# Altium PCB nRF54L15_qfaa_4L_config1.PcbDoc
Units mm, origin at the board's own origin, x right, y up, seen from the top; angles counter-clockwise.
Board outline 15 x 13 mm, 4 copper layers (Top Layer, Mid-Layer 1, Mid-Layer 2, Bottom Layer), stack 1.54 mm thick; 22 components, 46 nets, 93 pads, 72 vias.
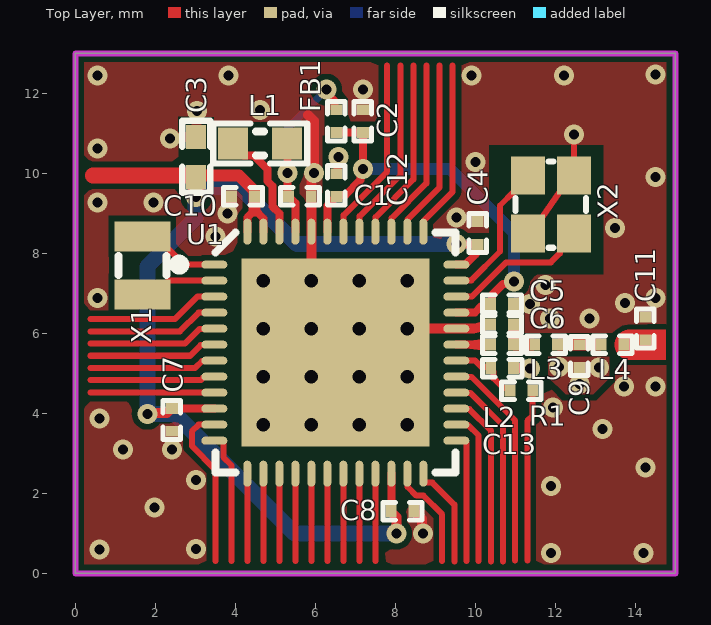
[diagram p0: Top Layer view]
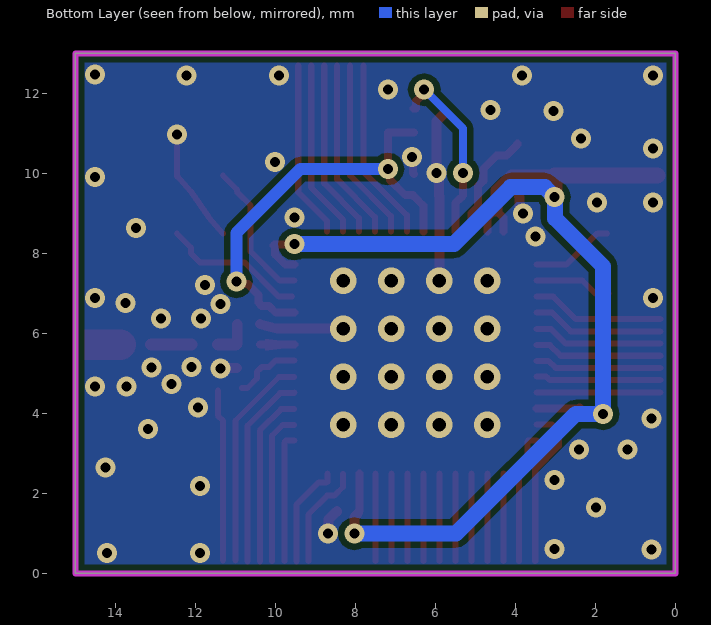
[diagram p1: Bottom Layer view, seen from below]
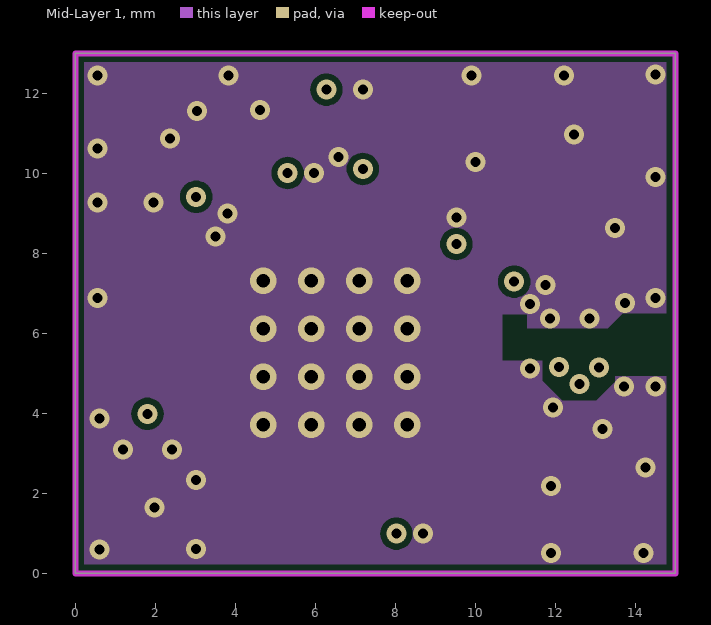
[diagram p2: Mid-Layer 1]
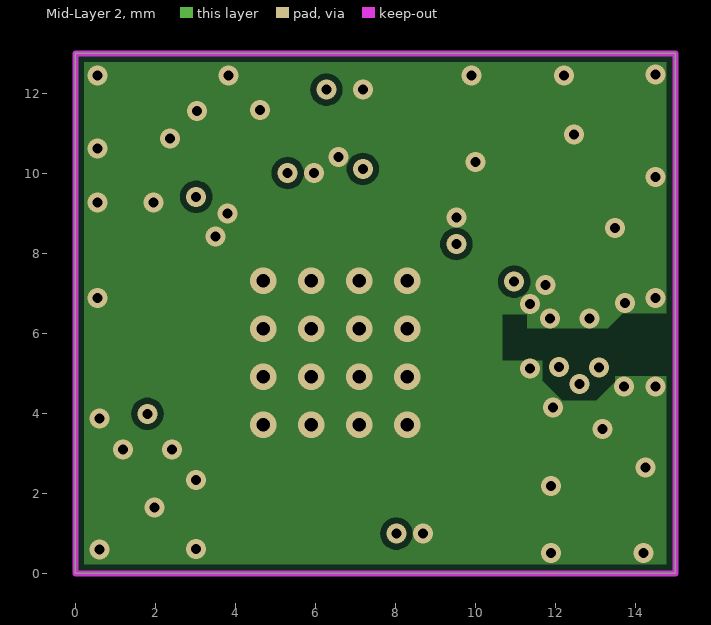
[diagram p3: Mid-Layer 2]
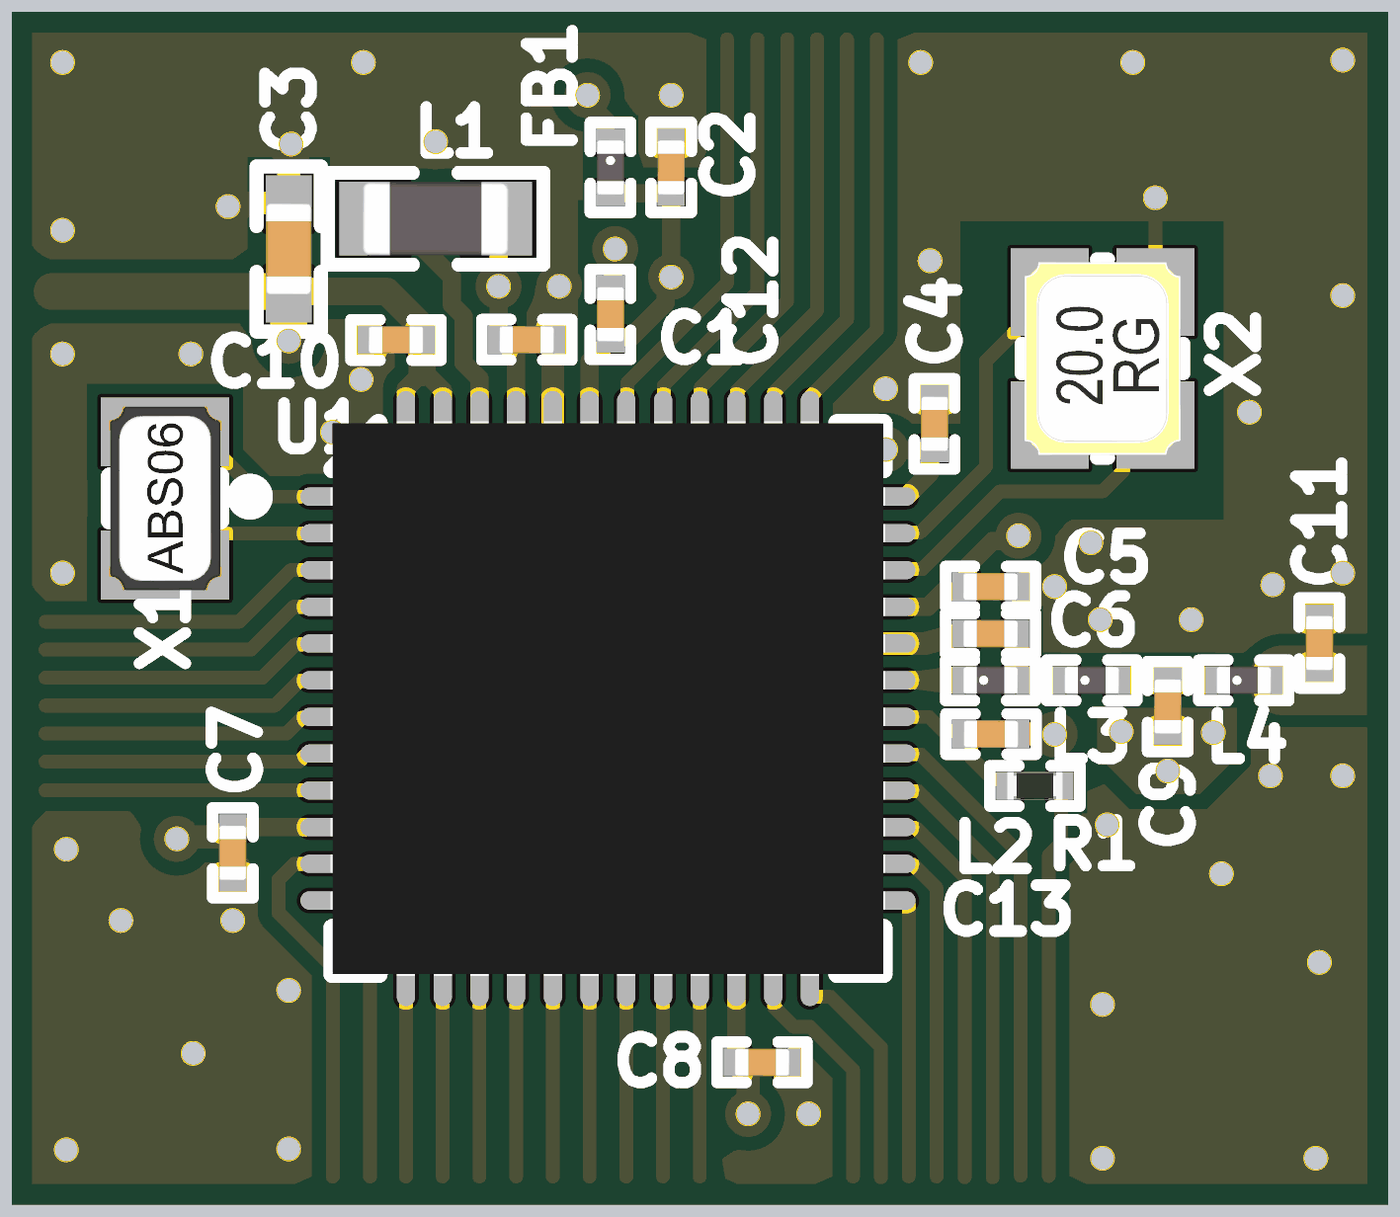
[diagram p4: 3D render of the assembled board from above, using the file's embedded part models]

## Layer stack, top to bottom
Top Solder: solder mask 0.0102, Solder Resist, Dk 3.5
Top Layer: signal copper 0.035
Dielectric 1: prepreg 0.1, PP-018, Dk 4.3
Mid-Layer 1: signal copper 0.035
Dielectric 2: core 1.2, Core-042, Dk 4.6
Mid-Layer 2: signal copper 0.035
Dielectric 3: prepreg 0.1, PP-018, Dk 4.3
Bottom Layer: signal copper 0.035
Bottom Solder: solder mask 0.0102, Solder Resist, Dk 3.5

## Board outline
0,0 0,13 15,13 15,0

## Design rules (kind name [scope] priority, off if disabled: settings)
Clearance Polygon_ANT [(InNamedPolygon('Top_Layer-GND')) or IsFill or IsRegion vs InNet('RF')] p1: gap=0.127 ignorepadtopadclearanceinfootprint=FALSE
Clearance Polygon [(InNamedPolygon('Top_Layer-GND'))  or (InNamedPolygon('Bottom_Layer-GND'))] p2: gap=0.15 ignorepadtopadclearanceinfootprint=FALSE
Clearance [All] p3: gap=0.15 ignorepadtopadclearanceinfootprint=FALSE
ComponentClearance [All] p1 off: gap=0.254 collisioncheckmode=3 verticalgap=0.254 showdistances=FALSE
FabricationTestPointUsage TestPointUsage [All] p1: valid=0 allowmultiple=FALSE
FabricationTestpoint Testpoint [All] p1: side=3 testpointundercomponent=TRUE minsize=1.016 maxsize=2.54 preferedsize=1.524 minholesize=0 maxholesize=1.016 preferedholesize=0.813 testpointgrid=0.025 allowsidetop=TRUE allowsidebottom=TRUE usegrid=TRUE gridtolerance=0
Height [All] p1 off: minheight=0 maxheight=25.4 prefheight=12.7
HoleSize [All] p1: absolutevalues=TRUE maxlimit=4.064 minlimit=0.2 maxpercent=80.000 minpercent=20.000
HoleToHoleClearance [All] p1: gap=0.36 allowstackedmicrovias=TRUE
MinimumAnnularRing [All] p1 off: minimumring=0.152
MinimumSolderMaskSliver [All] p1: minsoldermaskwidth=0.11
PlaneClearance [All] p1: clearance=0.2
PolygonConnect PolygonConnect_SMD_PADs [InComponent('C1','C2','C4','C5','C7','C8','C9','C10','C11') vs InNet('GND')] p1: connectstyle=Direct reliefconductorwidth=0.254 reliefentries=4 polygonreliefangle="90 Angle" airgapwidth=0.254
PolygonConnect PolygonConnect_GND_VIAs [isVia and innet(gnd)] p2: connectstyle=Direct reliefconductorwidth=0.254 reliefentries=4 polygonreliefangle="90 Angle" airgapwidth=0.254
PolygonConnect [All] p3: thpad.connectstyle=Relief thpad.reliefconductorwidth=0.25 thpad.reliefentries=4 thpad.polygonreliefangle="90 Angle" thpad.airgapwidth=0.2 smdpad.connectstyle=Relief smdpad.reliefconductorwidth=0.25 smdpad.reliefentries=4 smdpad.polygonreliefangle="90 Angle" smdpad.airgapwidth=0.2 via.connectstyle=Direct via.reliefconductorwidth=0.254 via.reliefentries=4 via.polygonreliefangle="90 Angle" via.airgapwidth=0.254
RoutingVias [All] p1: holewidth=0.406 width=0.813 viastyle="Through Hole" minholewidth=0.2 minwidth=0.4 maxholewidth=0.711 maxwidth=1.27
SilkToSolderMaskClearance SilkscreenOverComponentPads [IsPad] p1: minsilkscreentomaskgap=0.254 clearancetoexposedcopper=TRUE
SolderMaskExpansion SolderMaskExpansion_via [IsVia] p1: expansion=0.102 istentingtop=TRUE
SolderMaskExpansion [All] p2: expansion=0.04 istentingtop=FALSE
SupplyNets "Schematic Supply Nets_2" [InNet('GND')] p1: voltage=0.000
SupplyNets "Schematic Supply Nets" [InNet('VDD_nRF')] p2: voltage=0.000
Width [All] p1: maxlimit=2.54 minlimit=0.15 preferedwidth=0.15
21 further rules are at their usual default settings.

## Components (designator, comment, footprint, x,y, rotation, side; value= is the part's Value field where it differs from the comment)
C1 "2.2µF" CAPC0603X03L_C 5.615,9.425 r180 top
C2 "2.2µF" CAPC0603X03L_C 7.188,11.303 r270 top
C3 "10µF" CAPC1005X04L 3.023,10.414 r270 top
C4 "100nF" CAPC0603X03L_C 10.058,8.509 r90 top
C5 "10nF" CAPC0603X03L_C 10.668,6.735 r180 top
C6 "1.5pF" CAPC0603X03L_C 10.668,6.223 r0 top
C7 "100nF" CAPC0603X03L_C 2.413,3.835 r270 top
C8 "100nF" CAPC0603X03L_C 8.179,1.554 r0 top
C9 "2.0pF" CAPC0603X03L_C 12.598,5.43 r90 top
C10 "100nF" CAPC0603X03L_C 4.191,9.423 r180 top
C11 "0.3pF" CAPC0603X03L_C 14.249,6.121 r270 top
C12 "10nF" CAPC0603X03L_C 6.528,9.703 r270 top
C13 "3.9pF" CAPC0603X03L_C 10.673,5.13 r180 top
FB1 "120R/0.2A" INDC0603X03L_C 6.528,11.303 r270 top
L1 "4.7µH" INDC1608X06L 4.623,10.744 r0 top
L2 "2.7nH" INDC0603X03L_C 10.668,5.715 r0 top
L3 "3.5nH" INDC0603X03L_C 11.77,5.715 r0 top
L4 "3.5nH" INDC0603X03L_C 13.426,5.715 r0 top
R1 "1k" RESC0603X03L_C 11.151,4.564 r0 top
U1 "nRF54L15-QFAABB0" QFN40P600X600X90-48N 6.5,5.516 r0 top locked
X1 "32.768kHz" XTAL_2012 1.676,7.696 r90 top
X2 "32MHz" BT-XTAL_2016 11.887,9.22 r90 top

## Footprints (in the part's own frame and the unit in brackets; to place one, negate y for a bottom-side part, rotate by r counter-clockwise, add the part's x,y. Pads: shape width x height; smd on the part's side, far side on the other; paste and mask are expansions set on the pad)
BT-XTAL_2016 [mm] "Crystal 2.0 x 1.6 mm"
  rect 0.95x0.85 smd: 1(-0.725,-0.575) 2(0.725,-0.575) 3(0.725,0.575) 4(-0.725,0.575)
  silkscreen extent -1.08,-0.88 1.08,0.88, body extent -1.05,-0.85 1.05,0.85, height 0.56
CAPC0603X03L_C [mm] "Chip Capacitor, 2-Leads, Body 0.6x0.3mm, IPC High Density"
  rect 0.27x0.3 smd mask+0.05: 1(-0.285,0) 2(0.285,0)
  silkscreen extent -0.49,-0.22 0.49,0.22, body extent -0.3,-0.15 0.3,0.15, height 0.3
CAPC1005X04L [mm] "Chip Capacitor, 2-Leads, Body 1.0x0.5mm, IPC High Density"
  rect 0.6x0.5 smd: 1(-0.5,0) 2(0.5,0)
  silkscreen extent -0.9,-0.35 0.9,0.35, body extent -0.5,-0.25 0.5,0.25, height 0.5
INDC0603X03L_C [mm] "Chip Inductor, 2-Leads, Body 0.6x0.3mm, IPC High Density"
  rect 0.27x0.3 smd: 1(-0.285,0) 2(0.285,0)
  silkscreen extent -0.49,-0.22 0.49,0.22, body extent -0.3,-0.15 0.3,0.15, height 0.3
INDC1608X06L [mm] "Chip Inductor, 2-Leads, Body 1.6x0.8mm, IPC High Density"
  rect 0.75x0.8 smd: 1(-0.675,0) 2(0.675,0)
  silkscreen extent -1.17,-0.5 1.17,0.5, body extent -0.8,-0.4 0.8,0.4, height 0.8
QFN40P600X600X90-48N [mm] "QFN, 48-Leads, Body 6,0x6,0mm (max), Pitch 0,40mm, IPC Medium Density"
  oval 0.65x0.2 smd: 1(-3.025,2.2) 2(-3.025,1.8) 3(-3.025,1.4) 4(-3.025,1) 5(-3.025,0.6) 6(-3.025,0.2) 7(-3.025,-0.2) 8(-3.025,-0.6) 9(-3.025,-1) 10(-3.025,-1.4) 11(-3.025,-1.8) 12(-3.025,-2.2) 25(3.025,-2.2) 26(3.025,-1.8) 27(3.025,-1.4) 28(3.025,-1) 29(3.025,-0.6) 30(3.025,-0.2) 31(3.025,0.2) 32(3.025,0.6) 33(3.025,1) 34(3.025,1.4) 35(3.025,1.8) 36(3.025,2.2)
  oval 0.2x0.65 smd: 13(-2.2,-3.025) 14(-1.8,-3.025) 15(-1.4,-3.025) 16(-1,-3.025) 17(-0.6,-3.025) 18(-0.2,-3.025) 19(0.2,-3.025) 20(0.6,-3.025) 21(1,-3.025) 22(1.4,-3.025) 23(1.8,-3.025) 24(2.2,-3.025) 37(2.2,3.025) 38(1.8,3.025) 39(1.4,3.025) 40(1,3.025) 41(0.6,3.025) 42(0.2,3.025) 43(-0.2,3.025) 44(-0.6,3.025) 45(-1,3.025) 46(-1.4,3.025) 47(-1.8,3.025) 48(-2.2,3.025)
  rect 4.7x4.7 smd: 49(0,0)
  silkscreen extent -4.02,-3 3,3, body extent -3.02,-3.02 3.02,3.02, height 0.86
RESC0603X03L_C [mm] "Chip Resistor, 2-Leads, Body 0.6x0.3mm, IPC High Density"
  rect 0.27x0.3 smd: 1(-0.285,0) 2(0.285,0)
  silkscreen extent -0.49,-0.22 0.49,0.22, body extent -0.3,-0.15 0.3,0.15, height 0.23
XTAL_2012 [mm] "XTAL SMD 2.0 x 1.2 mm"
  rect 0.75x1.4 smd: 1(-0.725,0) 2(0.725,0)
  silkscreen extent -0.24,-0.6 0.24,0.6, body extent -1,-0.61 1,0.61, height 0.6

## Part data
C1 C2: library part C0201-2µ2-2.5V-X6T-GRM033D80E225ME47D, "Capacitor, Ceramic, 2.2µF 2.5V X6T 0201,±20%", Manufacturer=Murata, Manufacturer Part Number=GRM033R61A225KE47, Part number IPS=N.A., Part number NEMS=100200527, Supplier Part Number 1=81-GRM033D80E225ME7D
C3: library part C0402-10µF-6.3V-X6S, "Capacitor, X6S, ±20%, 6.3V", Manufacturer=N.A., Part number NEMS=100200478
C4 C7 C8 C10: library part C0201-100n-10V-X7R, "Capacitor, X7R, ±10%", Manufacturer=N.A., Part number NEMS=100200469
C5 C12: library part C0201-10n-6.3V-X7R, "Capacitor, X7R, 6.3V", Manufacturer=Murata, Manufacturer Part Number=GRM033R70J103KA01D, Part number IPS=N.A., Part number NEMS=100200407, Supplier Part Number 1=490-1262-1-ND
C6: library part C0201-1.5p-25V-NP0-GJM0335C1E1R5WB01, "Capacitor, NP0, ±0.05pF, 25V, High Q", Manufacturer=Murata, Manufacturer Part Number=GJM0335C1E1R5WB01, Part number IPS=N.A., Part number NEMS=100200477, Supplier Part Number 1=490-11176-2-ND
C9: library part C0201-2.0p-HQ-Murata, "Capacitor, NP0, ±0.05pF, 25V", Manufacturer=Murata, Manufacturer Part Number=GJM0335C1E2R0WB01, Part number IPS=00000001775, Part number NEMS=100200419, Part number Norautron=N.A.
C11: library part C0201-0.3p-50V-GRM0335C1HR30BA01, "Capacitor, C0G, ±0.1pF, 50V", Manufacturer=Murata, Manufacturer Part Number=GRM0335C1HR30BA01, Part number IPS=N.A., Part number NEMS=100200650, Supplier Part Number 1=490-6135-2-ND
C13: library part C0201-3.9p, "Chip Cap 0201", Manufacturer=N.A., Part number NEMS=100200024
FB1: library part FB0201-120R@100M-200mA-BLM03AG121SN1D, "Ferrite Bead, 120 Ohm @ 100MHz, 200mA, 500 mOhm Max", Manufacturer=Murata, Manufacturer Part Number=BLM03AG121SN1D, Part number IPS=N.A., Part number NEMS=100300419, Supplier Part Number 1=490-5622-1-ND
L1: library part L0603-4µ7-MLZ1608M4R7WT000, "Inductor, 120mA, ±20%, 0.65R", Manufacturer="TDK Corporation", Manufacturer Part Number=MLZ1608M4R7WT000, Part number IPS=N.A., Part number NEMS=100300440, Supplier Part Number 1=445-6390-2-ND
L2: library part L0201-2n7-HQ-Murata, "Inductor, 600mA, ±0.1ｎH, 120mOhm", Manufacturer=Murata, Manufacturer Part Number=LQP03HQ2N7B02, Part number IPS=00000001753, Part number NEMS=100300214, Part number Norautron=N.A., Supplier Part Number 1=490-13909-1-ND
L3 L4: library part L0201-3n5-HQ-Murata, "Inductor, 500mA, ±0.1ｎH, 170mOhm", Manufacturer=Murata, Manufacturer Part Number=LQP03HQ3N5B02, Part number IPS=N.A., Part number NEMS=100300222, Supplier Part Number 1=490-13925-1-ND
R1: library part R0201-1k0, "Resistor, ±1%, 0.05W", Manufacturer=N.A., Part number IPS=00000005786, Part number NEMS=100100043
U1: "Multi-protocol Bluetooth Low Energy, IEEE 802.15.4, ANT and 2.4GHz proprietary system-on-chip", Manufacturer="Nordic Semiconductor", Part number IPS=N.A., Part number NEMS=102000348
X1: library part XTAL_SMD2012_32.768kHz_9pF_TXC, "XTAL SMD 2012, 32.768kHz, 9pF, ±20ppm", Manufacturer="TXC Corporation", Manufacturer Part Number=9HT11-32.768KDZC-T, Part number IPS=N.A., Part number NEMS=101600107, Supplier Part Number 1=887-1426-2-ND
X2: library part XTAL_SMD2016_32MHz_8pF_Kyocera, "XTAL SMD 2016, 32MHz, Cl=8pF, Tot: ±40ppm", Manufacturer=Kyocera, Manufacturer Part Number=CX2016DB32000D0WZRC1, Part number IPS=00000007827, Part number NEMS=101600039, Part number Norautron=26511136, Supplier Part Number 1=1253-1586-1-ND

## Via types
v1: diameter 0.5, hole 0.25, Top Layer to Bottom Layer, tented both sides, 56 vias
v2: diameter 0.66, hole 0.33, Top Layer to Bottom Layer, tented both sides, 16 vias

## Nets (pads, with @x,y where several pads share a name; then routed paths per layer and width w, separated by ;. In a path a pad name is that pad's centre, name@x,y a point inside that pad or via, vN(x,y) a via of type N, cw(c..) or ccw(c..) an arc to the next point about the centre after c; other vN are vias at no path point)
DCC: L1.1 U1.46 | length 2.8
  Top Layer w0.2: L1.1 3.948,10.719 4.223,10.444 4.466,10.444 4.801,10.109 4.801,9.804 4.928,9.677 4.928,9.172 5.1,9 U1.46
DECA: C2.2 C5.2 C12.2 FB1.2 U1.33 U1.43 | length 11.2
  Top Layer w0.2: U1.43 6.3,9.19 C12.2 6.563,9.453 6.75,9.453 7.131,9.833 7.131,10.052 v1(7.188,10.109) C2.2 ; FB1.2 C2.2@7.188,11.018 ; U1.33 9.988,6.516 10.157,6.685 10.348,6.685 10.383,6.72 C5.2 ; C5.2@10.383,6.731 10.418,6.766 10.418,6.961 10.689,7.232 10.915,7.232 v1(10.973,7.29)
  Bottom Layer w0.3: v1(7.188,10.109) 9.373,10.109 10.973,8.509 v1(10.973,7.29)
DECD: C1.2 FB1.1 L1.2 U1.45 | length 5.4
  Top Layer w0.2: L1.2@5.309,10.784 5.309,9.446 C1.2 5.33,9.41 5.365,9.375 5.38,9.375 5.5,9.255 5.5,8.766 U1.45 ; v1(6.278,12.09) 6.278,12.009 6.478,11.809 6.478,11.623 FB1.1@6.544,11.623
  Bottom Layer w0.2: v1(5.309,10.008) 5.309,11.125 6.274,12.09 v1(6.278,12.09)
GND: C1.1 C2.1 C3.1 C4.2 C5.1 C6.1 C7.2 C8.2 C9.1 C10.2 C11.1 C12.1 C13.1 U1.32 U1.44 U1.49 X2.2 X2.4 | length 11.2
  Top Layer w0.15: X2.4 11.662,8.895 12.112,9.545 X2.2 ; X2.2@12.462,9.92 v1(12.462,10.973)
  Top Layer w0.2: C12.1 6.553,10.013 6.553,10.389 v1(6.579,10.414)
  Top Layer w0.25: v1(3.81,8.992) 3.81,9.059 3.896,9.145 3.896,9.413 C10.2 ; 5.817,11.455 5.969,11.303 5.969,9.94 5.91,9.881 5.91,9.435 C1.1 U1.44 v2(5.9,7.316) ; U1.49@8.303,6.116 U1.32 9.954,6.116 C6.1@10.381,6.23 ; C8.2 8.464,1.539 8.474,1.529 8.489,1.529 8.665,1.353 8.665,1.013 v1(8.687,0.991) ; C13.1 v1@11.361,5.13
  other v1: 11.887,0.508 14.211,0.508 0.6,0.6 3.023,0.61 1.981,1.651 11.887,2.184 3.023,2.337 14.249,2.642 1.194,3.099 2.413,3.099 13.183,3.607 0.6,3.875 11.938,4.14 13.716,4.674 14.503,4.674 12.598,4.727 11.366,5.125 13.094,5.145 12.091,5.156 11.862,6.375 12.852,6.375 11.366,6.736 13.741,6.756 0.559,6.883 14.503,6.883 11.76,7.214 3.5,8.418 13.487,8.636 9.525,8.89 0.559,9.271 1.956,9.271 14.503,9.906 5.969,10.008 10.008,10.287 0.559,10.617 2.362,10.877 3.048,11.557 4.623,11.582 7.188,12.09 0.559,12.446 3.835,12.446 9.906,12.446 12.217,12.446 14.503,12.471
  other v2: 4.7,3.716 5.9,3.716 7.1,3.716 8.3,3.716 4.7,4.916 5.9,4.916 7.1,4.916 8.3,4.916 4.7,6.116 5.9,6.116 7.1,6.116 8.3,6.116 4.7,7.316 7.1,7.316 8.3,7.316
NetC6_2: C6.2 L2.2 L3.1 | length 0.9
  Top Layer w0.27: L2.2@10.953,5.73 C6.2
  Top Layer w0.3: L2.2@10.98,5.715 L3.1@11.43,5.715
NetC9_2: C9.2 L3.2 L4.1 | length 1
  Top Layer w0.3: L3.2@12.091,5.715 C9.2 L4.1@13.106,5.715
NetC13_2: C13.2 R1.1 U1.30 | length 1.7
  Top Layer w0.15: U1.30 9.997,5.316 10.152,5.161 10.335,5.161 C13.2@10.385,5.111 ; C13.2@10.384,5.103 10.4,5.103 10.456,5.047 10.456,4.976 10.457,4.974 10.457,4.873 10.696,4.634 R1.1@10.836,4.634
NetL2_1: L2.1 U1.31 | length 0.9
  Top Layer w0.2: U1.31 10.382,5.716 L2.1
NRESET: R1.2 | length 4.3
  Top Layer w0.15: 11.303,0.315 11.303,3.81 11.436,3.943 R1.2
P0.00: U1.23 | length 2.6
  Top Layer w0.15: U1.23@8.309,2.482 8.309,2.157 8.527,1.939 8.703,1.939 9.169,1.473 9.169,0.308
P0.01: U1.24 | length 2.6
  Top Layer w0.15: U1.24 8.7,2.289 8.723,2.266 8.925,2.266 9.474,1.717 9.474,0.301
P0.02: U1.27 | length 4.3
  Top Layer w0.15: U1.27@9.535,4.106 9.853,4.106 10.386,3.573 10.386,0.301
P0.03: U1.28 | length 4.9
  Top Layer w0.15: U1.28 9.535,4.506 9.881,4.506 10.691,3.696 10.691,0.301
P0.04: U1.29 | length 5.4
  Top Layer w0.15: U1.29@9.534,4.907 9.909,4.907 10.996,3.82 10.996,0.318
P1.00/XL1: U1.1 X1.2 | length 2.1
  Top Layer w0.15: X1.2@1.702,8.497 1.951,8.497 2.301,8.147 2.301,8.138 2.723,7.716 U1.1
P1.01/XL2: U1.2 X1.1 | length 1.9
  Top Layer w0.15: X1.1@1.676,6.997 2.001,6.997 2.321,7.316 U1.2
P1.02/NFC1: U1.3 | length 3.3
  Top Layer w0.15: 0.375,6.354 2.487,6.354 3.049,6.916 U1.3
P1.03/NFC2: U1.4 | length 3.3
  Top Layer w0.152: 0.375,6.049 2.614,6.049 3.08,6.516 U1.4
P1.04/AIN0: U1.5 | length 3.2
  Top Layer w0.152: 0.375,5.745 2.741,5.745 3.103,6.107 U1.5@3.466,6.107
P1.05/AIN1: U1.6 | length 3.2
  Top Layer w0.152: 0.375,5.44 2.868,5.44 3.135,5.707 U1.6@3.466,5.707
P1.06/AIN2: U1.7 | length 3.2
  Top Layer w0.152: 0.375,5.135 2.995,5.135 3.167,5.307 U1.7@3.466,5.307
P1.07/AIN3: U1.8 | length 3.1
  Top Layer w0.152: 0.375,4.83 3.137,4.83 3.199,4.892 3.213,4.892 3.237,4.916 U1.8
P1.08: U1.9 | length 3.1
  Top Layer w0.152: 0.375,4.516 U1.9
P1.09: U1.37 | length 4.4
  Top Layer w0.152: U1.37@8.709,8.55 8.709,8.811 9.428,9.529 9.428,12.698
P1.10: U1.38 | length 4.5
  Top Layer w0.152: U1.38@8.309,8.55 8.309,8.85 9.103,9.643 9.103,12.698
P1.11: U1.39 | length 4.5
  Top Layer w0.152: U1.39@7.909,8.55 7.909,8.877 8.778,9.746 8.778,12.698
P1.12: U1.40 | length 4.5
  Top Layer w0.15: U1.40@7.51,8.551 7.51,8.904 8.453,9.847 8.453,12.699
P1.13: U1.41 | length 4.6
  Top Layer w0.15: U1.41@7.11,8.551 7.11,8.928 8.128,9.946 8.128,12.699
P1.14: U1.42 | length 4.6
  Top Layer w0.15: U1.42@6.71,8.551 6.71,8.952 7.798,10.041 7.798,12.699
P2.00: U1.11 | length 4.1
  Top Layer w0.152: U1.11 3.081,3.716 2.912,3.547 2.912,3.184 3.503,2.593 3.503,0.309
P2.01: U1.12 | length 3.3
  Top Layer w0.15: U1.12 3.677,3.316 3.7,3.293 3.7,2.906 3.909,2.697 3.909,0.309
P2.02: U1.13 | length 2.2
  Top Layer w0.15: 4.3,0.309 U1.13
P2.03: U1.14 | length 2.2
  Top Layer w0.15: 4.7,0.309 U1.14
P2.04: U1.15 | length 2.2
  Top Layer w0.15: 5.1,0.309 U1.15
P2.05: U1.16 | length 2.2
  Top Layer w0.15: 5.5,0.309 U1.16
P2.06: U1.17 | length 2.2
  Top Layer w0.15: 5.9,0.309 U1.17
P2.07: U1.18 | length 2.2
  Top Layer w0.15: 6.3,0.309 U1.18
P2.08: U1.19 | length 2.2
  Top Layer w0.15: 6.7,0.309 U1.19
P2.09: U1.20 | length 2.2
  Top Layer w0.15: 7.1,0.309 U1.20
P2.10: U1.21 | length 2.2
  Top Layer w0.15: 7.5,0.309 U1.21
RF: C11.2 L4.2 | length 0.5
  Top Layer w0.762: 13.86,5.715 C11.2@14.367,5.715
SWDCLK: U1.26 | length 3.8
  Top Layer w0.15: U1.26@9.535,3.706 9.822,3.706 10.081,3.447 10.081,0.309
SWDIO: U1.25 | length 3.2
  Top Layer w0.15: U1.25 9.736,3.316 9.777,3.276 9.777,0.311
VDD_NRF: C3.2 C4.1 C7.1 C8.1 C10.1 U1.10 U1.22 U1.36 U1.47 U1.48 | length 31.6
  Top Layer w0.2: C7.1@2.398,4.12 C7.1 ; C7.1@2.417,4.116 U1.10 ; U1.48 4.3,8.892 4.476,9.068 4.491,9.084 4.7,8.875 U1.47 ; C8.1 7.929,1.519 C8.1@7.929,1.504 ; C8.1@7.9,1.554 U1.22 ; U1.36 9.75,7.716 9.75,7.718 10.008,7.976 C4.1@10.008,8.164 ; v1(9.525,8.23) 9.534,8.221 10.021,8.221 C4.1@10.043,8.199
  Top Layer w0.25: v1(1.803,3.988) 1.825,4.01 2.287,4.01 C7.1@2.398,4.12 ; C8.1@7.929,1.504 8.026,1.406 v1(8.026,0.991)
  Top Layer w0.3: C3.2@2.973,9.951 3.023,9.951 4.09,9.951 4.476,9.566 C10.1 4.476,9.068
  Top Layer w0.4: 0.445,9.951 C3.2@2.946,9.951 ; v1(3.023,9.413) C3.2@3.023,9.951
  Bottom Layer w0.4: v1(1.803,3.988) 2.489,3.988 5.486,0.991 v1(8.026,0.991) ; v1@1.803,4.034 1.803,7.671 3.003,8.871 v1@3.003,9.394 ; v1@3.05,9.413 v1(3.023,9.413) 3.261,9.652 4.115,9.652 5.537,8.23 v1(9.525,8.23)
XC1: U1.34 X2.1 | length 3.6
  Top Layer w0.15: U1.34@9.586,6.926 9.923,6.926 10.77,7.772 11.887,7.772 12.112,7.997 12.112,8.145 X2.1
XC2: U1.35 X2.3 | length 3.6
  Top Layer w0.15: U1.35 9.535,7.326 9.899,7.326 10.617,8.044 10.617,9.195 10.962,9.54 10.962,9.595 X2.3

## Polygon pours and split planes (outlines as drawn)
GND on Top Layer "GND_island" (solid, pour order 1000): 11.776,5.414 11.776,4.905 12.207,4.473 12.893,4.473 13.299,4.878 13.299,5.413
GND on Top Layer "Top_Layer-GND" (solid, remove dead copper, pour order 1004): 0,13 0,0 15,0 15,13
GND on Bottom Layer "Bottom_Layer-GND" (solid, remove dead copper, pour order 1001): 0,13 0,0 15,0 15,13
GND on Mid-Layer 1 "Top_Layer-GND" (solid, remove dead copper, pour order 1002): 0,13 0,0 15,0 15,13
GND on Mid-Layer 2 "Top_Layer-GND" (solid, remove dead copper, pour order 1003): 0,13 0,0 15,0 15,13

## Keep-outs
Keep-Out Layer:
  the board outline again, w0.152

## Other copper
Top Layer:
  rectangle net RF: 14.3,5.334 14.765,6.096
  pour cut-out: 11.826,5.413 11.826,4.905 12.258,4.473 12.944,4.473 13.35,4.879 13.35,4.88 13.35,5.413 13.5,5.413 13.5,4.793 13.018,4.31 12.179,4.31 11.671,4.818 11.671,5.413
  pour cut-out: 10.705,6.786 10.705,6.577 10.818,6.577 10.818,6.786
  region net NetL2_1: 10.248,5.865 9.859,5.815 9.859,5.616 10.248,5.565
  pour cut-out: 6.985,9.601 6.172,9.601 6.172,10.947 6.985,10.947
  pour cut-out: 0.833,7.904 0.833,7.493 0.945,7.493 0.945,7.904
  pour cut-out: 4.753,11.278 4.543,11.278 4.543,11.165 4.753,11.165
  pour cut-out: 13.206,10.718 13.206,7.463 10.338,7.463 10.338,10.718
Mid-Layer 1:
  pour cut-out: 11.671,5.309 11.671,4.818 12.179,4.31 13.018,4.31 13.5,4.793 13.5,5.309
  pour cut-out: 10.668,6.477 10.668,5.309 13.005,5.309 13.386,4.928 15,4.928 15,6.502 13.691,6.502 13.31,6.121 11.303,6.121 11.303,6.477
Mid-Layer 2:
  pour cut-out: 11.671,5.309 11.671,4.818 12.179,4.31 13.018,4.31 13.5,4.793 13.5,5.309
  pour cut-out: 10.668,6.477 10.668,5.309 13.005,5.309 13.386,4.928 15,4.928 15,6.502 13.691,6.502 13.31,6.121 11.303,6.121 11.303,6.477

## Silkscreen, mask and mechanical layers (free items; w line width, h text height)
Mechanical 1:
  the board outline again, w0.152

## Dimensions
15,13 to 15,0 on Mechanical 3
0,0 to 15,0 on Mechanical 3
